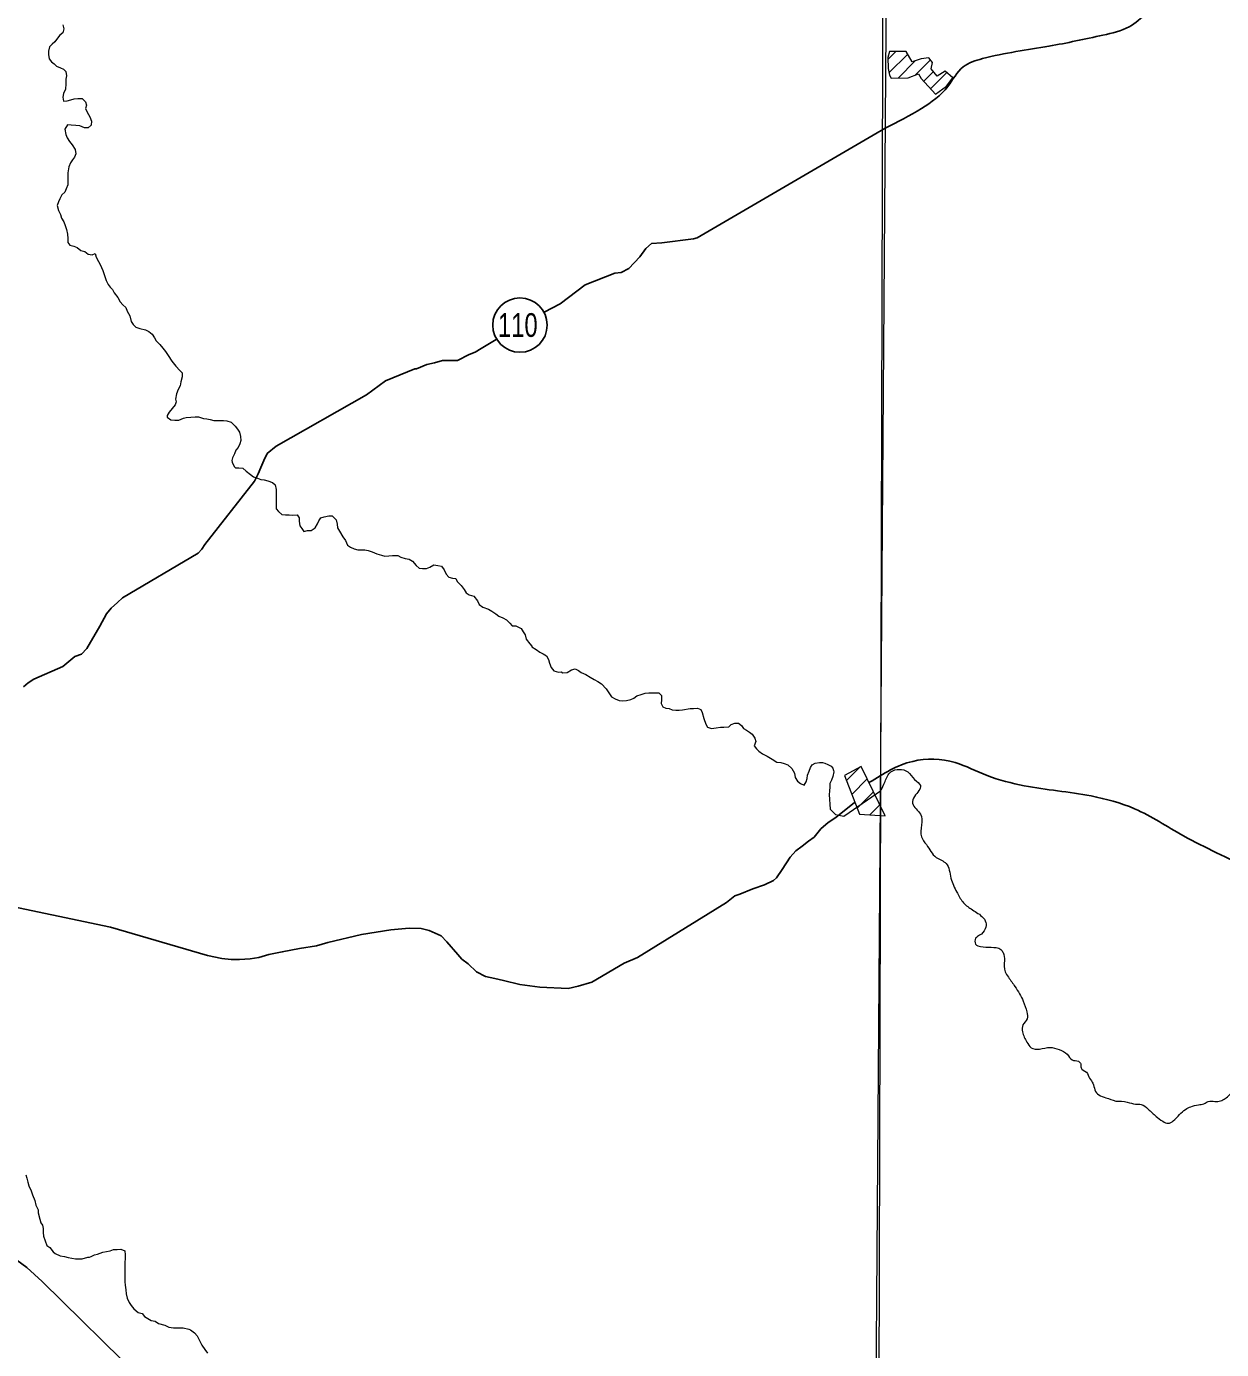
# Model space of a CAD drawing. Extents: x -1643653 to 4543381, y 1624270 to 13878484.
# Drawn here: x 615998 to 619526, y 8902830 to 8906736 of the extents above; entities that cross this region are included whole.
import ezdxf
from ezdxf.enums import TextEntityAlignment as Align

# ---------------------------------------------------------------- set-up
doc = ezdxf.new("R2010")
doc.units = 0
doc.header["$LTSCALE"] = 200
doc.layers.add('6', color=7, linetype='Continuous', lineweight=13)
doc.layers.add('60', color=7, linetype='Continuous', lineweight=13)

msp = doc.modelspace()

# ---------------------------------------------------------------- linework, layer by layer
at = {"layer": '6'}
for p, q in [((618541.3, 8906638.8), (618565.2, 8906662.7)), ((618544.4, 8906599.4), (618599.8, 8906654.9)), ((618571.2, 8906583.9), (618623, 8906635.6)), ((618623.2, 8906593.4), (618667.4, 8906637.6)), ((618647.2, 8906575), (618675.6, 8906603.4)), ((618667.4, 8906552.7), (618715.2, 8906600.5)), ((618419.3, 8904510), (618459.5, 8904550.2)), ((618435.1, 8904469.2), (618480.5, 8904514.6)), ((618451, 8904428.5), (618499.1, 8904476.6)), ((618488.1, 8904409.1), (618517.7, 8904438.6))]:
    msp.add_line(p, q, dxfattribs=at)
for points in [[(618663, 8924716.1), (618558.3, 8909803.7), (618456.5, 8896026.7)], [(616107.9, 8906729.7), (616104.8, 8906717.5), (616096.6, 8906710.4), (616089.4, 8906702.3), (616081.2, 8906691.2), (616074, 8906684.1), (616065.8, 8906676), (616062.7, 8906663.8), (616062.6, 8906653.6), (616064.6, 8906641.3), (616071.6, 8906632.1), (616079.7, 8906626), (616086.8, 8906618.8), (616097.9, 8906614.6), (616107.1, 8906610.5), (616114.1, 8906603.3), (616116.1, 8906591.1), (616114, 8906580.9), (616113.9, 8906566.7), (616112.8, 8906551.4), (616107.6, 8906538.2), (616105.5, 8906528), (616107.4, 8906515.8), (616117.6, 8906516.7), (616128.8, 8906519.7), (616139, 8906522.7), (616149.2, 8906523.6), (616162.4, 8906523.6), (616172.5, 8906514.3), (616175.5, 8906504.1), (616172.4, 8906493.9), (616177.4, 8906483.7), (616185.4, 8906469.4), (616189.4, 8906457.2), (616189.3, 8906444.9), (616180.1, 8906436.8), (616168.9, 8906436.9), (616155.8, 8906443.1), (616143.6, 8906444.2), (616130.3, 8906445.3), (616119.2, 8906446.4), (616110.9, 8906433.2), (616113.9, 8906417.9), (616117.9, 8906407.7), (616124.9, 8906396.4), (616133, 8906387.2), (616142.1, 8906372.9), (616144, 8906360.7), (616139.9, 8906350.5), (616133.7, 8906342.4), (616127.6, 8906334.3), (616123.4, 8906322.1), (616120.2, 8906304.8), (616120.1, 8906290.5), (616120.1, 8906279.3), (616120, 8906269.1), (616114.8, 8906256.9), (616110.7, 8906246.8), (616102.5, 8906239.7), (616096.3, 8906227.5), (616092.2, 8906218.4), (616088, 8906208.2), (616092, 8906192.9), (616098, 8906181.7), (616101, 8906170.4)], [(616104.9, 8906740.9), (616107.9, 8906729.7)], [(616101, 8906170.4), (616108, 8906159.2), (616112, 8906149), (616116, 8906136.7), (616119, 8906123.4), (616119.9, 8906110.2), (616119.8, 8906099), (616125.9, 8906090.8), (616138.1, 8906087.7), (616147.2, 8906083.5), (616158.3, 8906075.3), (616170.5, 8906072.2), (616179.6, 8906064), (616191.8, 8906061.9), (616201, 8906065.9), (616204, 8906055.7), (616211, 8906042.4), (616215, 8906033.2), (616223, 8906015.8), (616229, 8905998.5), (616233, 8905986.2), (616239, 8905975), (616245.1, 8905966.8), (616252.1, 8905959.6), (616257.2, 8905950.4), (616267.2, 8905936.1), (616274.3, 8905923.8), (616282.3, 8905914.6), (616291.4, 8905906.4), (616295.4, 8905896.2), (616303.5, 8905881.8), (616307.4, 8905865.5), (616312.5, 8905856.3), (616320.5, 8905849.1), (616332.7, 8905845), (616349, 8905840.8), (616359.1, 8905835.6)], [(616359.1, 8905835.6), (616369.2, 8905828.4), (616376.3, 8905817.2), (616380.3, 8905808), (616391.4, 8905797.7), (616400.5, 8905786.5), (616408.5, 8905777.2), (616416.6, 8905765), (616426.7, 8905748.6), (616438.8, 8905733.2), (616450.9, 8905720.9), (616458, 8905713.8), (616457.9, 8905701.6), (616453.7, 8905687.3), (616451.6, 8905675.1), (616445.4, 8905664.9), (616441.2, 8905651.7), (616438.2, 8905636.4), (616439.5, 8905627.9), (616437, 8905619.4), (616419.4, 8905598.1), (616413.4, 8905587.8), (616413.3, 8905582.6), (616424.5, 8905575.4), (616435.6, 8905574.3), (616447.8, 8905574.3), (616461.1, 8905580.3), (616469.2, 8905581.7), (616483.5, 8905583.2), (616495.7, 8905584.1), (616505.6, 8905583.6), (616520.7, 8905578.7), (616530.4, 8905578.1), (616540.1, 8905575.7), (616551, 8905573.2), (616566.8, 8905573.2), (616579.5, 8905573.2), (616589.8, 8905572), (616602.6, 8905568.4), (616607.5, 8905563.1), (616614.5, 8905555.9), (616620.6, 8905547.7), (616626.6, 8905538.5), (616629.6, 8905526.2), (616630.5, 8905514), (616627.4, 8905503.8), (616623.2, 8905493.7), (616616.5, 8905485.2), (616611.7, 8905474.3), (616606.2, 8905463.3), (616604.4, 8905455.4), (616605, 8905450), (616611.1, 8905437.2), (616614.7, 8905433.6), (616624.9, 8905433.6), (616637.1, 8905432.5), (616646.2, 8905423.2), (616659.3, 8905414), (616668.4, 8905406.8), (616679.6, 8905402.6), (616689.8, 8905398.5), (616699.9, 8905397.4), (616710.1, 8905395.3), (616724.3, 8905390.1), (616732.4, 8905382.9)], [(616732.4, 8905382.9), (616735.3, 8905369.7), (616735.3, 8905359.5), (616735.2, 8905344.2), (616735, 8905325.9), (616734.9, 8905312.6), (616742, 8905304.4), (616752.1, 8905295.2), (616762.3, 8905294.1), (616773.5, 8905294.1), (616784.7, 8905294), (616796.9, 8905294.9), (616802.9, 8905285.7), (616802.8, 8905275.5), (616804.8, 8905262.3), (616810.8, 8905254.1), (616816.9, 8905244.9), (616828.1, 8905247.9), (616838.2, 8905247.8), (616850.5, 8905255.9), (616856.7, 8905268.1), (616860.8, 8905277.2), (616867, 8905285.3), (616877.2, 8905288.3), (616890.4, 8905291.3), (616900.6, 8905291.2), (616912.7, 8905279.9), (616915.7, 8905266.7), (616916.6, 8905256.5), (616921.7, 8905246.2), (616931.7, 8905229.9), (616939.8, 8905218.6), (616945.8, 8905205.3), (616954.9, 8905199.2), (616965, 8905194), (616976.2, 8905190.9), (616986.4, 8905190.8)], [(616986.4, 8905190.8), (616996.5, 8905190.7), (617006.7, 8905189.7), (617018.9, 8905185.5), (617032.1, 8905179.3), (617046.3, 8905175.1), (617056.4, 8905172), (617067.6, 8905173), (617078.8, 8905174.9), (617094.1, 8905174.8), (617103.2, 8905169.7), (617116.4, 8905165.5), (617127.6, 8905163.4), (617137.7, 8905158.2), (617148.8, 8905144.9), (617156.9, 8905136.7), (617167.1, 8905135.7), (617179.3, 8905135.6), (617188.5, 8905139.6), (617200.7, 8905146.6), (617212.9, 8905144.5), (617223.1, 8905143.4), (617231.1, 8905132.2), (617237.1, 8905118.9), (617245.2, 8905110.7), (617255.4, 8905107.6), (617265.5, 8905106.5), (617269.5, 8905097.3), (617281.7, 8905086), (617289.7, 8905073.7), (617295.8, 8905064.5), (617304.9, 8905058.4), (617319.1, 8905054.2), (617329.2, 8905040.9), (617334.2, 8905029.7), (617345.3, 8905022.4), (617361.6, 8905016.2), (617371.7, 8905010.1), (617383.8, 8905001.8), (617392.9, 8904995.7), (617404.1, 8904990.5), (617415.2, 8904984.3), (617425.3, 8904975.1), (617432.4, 8904966.9), (617442.6, 8904966.8), (617458.8, 8904958.6), (617464.8, 8904949.3), (617469.9, 8904940.1), (617472.8, 8904927.9), (617483.6, 8904913.2), (617490, 8904906.8), (617490, 8904904.7), (617503.1, 8904897.1), (617513.3, 8904888.9), (617523.5, 8904884.2), (617532.9, 8904877.9), (617539.1, 8904867), (617542.2, 8904856.1), (617546.9, 8904843.6), (617554.7, 8904834.2), (617568.8, 8904829.5), (617576.6, 8904831.1), (617581.2, 8904827.9), (617594.2, 8904829.3), (617607.5, 8904836.4)], [(617607.5, 8904836.4), (617617.7, 8904839.4), (617627.8, 8904835.2), (617635.9, 8904829.1), (617649.1, 8904822.9), (617662.3, 8904815.6), (617674.4, 8904808.4), (617684.6, 8904802.2), (617695.7, 8904795.1), (617709.9, 8904780.7), (617716.9, 8904769.4), (617725, 8904757.2), (617736.1, 8904751), (617748.3, 8904746.8), (617758.4, 8904745.8), (617769.6, 8904746.7), (617781.9, 8904749.7), (617791.1, 8904753.7), (617800.2, 8904759.7), (617812.5, 8904763.7), (617824.7, 8904767.7), (617835.9, 8904768.7), (617855.2, 8904768.6), (617865.4, 8904768.5), (617872.5, 8904761.3), (617872.4, 8904748.1), (617872.3, 8904737.9), (617876.3, 8904727.7), (617885.5, 8904723.5), (617895.6, 8904722.4), (617904.7, 8904718.3), (617914.9, 8904718.2), (617925.1, 8904718.2), (617935.3, 8904719.1), (617957.7, 8904723.1), (617967.8, 8904723), (617979, 8904724)], [(617979, 8904724), (617989.2, 8904719.8), (617993.2, 8904710.6), (617998.2, 8904693.3), (618004.1, 8904676.9), (618008.2, 8904667.7), (618020.3, 8904663.6), (618034.6, 8904665.5), (618046.8, 8904667.5), (618057, 8904667.4), (618071.2, 8904668.3), (618078.4, 8904675.4), (618089.6, 8904679.4), (618099.8, 8904679.4), (618108.9, 8904672.2), (618114.9, 8904664), (618124.1, 8904658.8), (618132.2, 8904652.7), (618140.2, 8904646.5), (618148.3, 8904635.3), (618151.3, 8904625.1), (618146.1, 8904612.9), (618153.2, 8904603.6), (618160.2, 8904596.5), (618171.4, 8904589.3), (618184.6, 8904582.1), (618199.8, 8904572.8), (618212.9, 8904564.6), (618225.1, 8904563.4), (618235.3, 8904560.3), (618245.4, 8904556.2), (618257.6, 8904545.9), (618265.6, 8904531.6), (618267.5, 8904519.4), (618274.6, 8904508.1), (618283.7, 8904500.9), (618293.8, 8904496.8), (618300, 8904505.9), (618303.1, 8904516.1), (618304.2, 8904526.3), (618309, 8904537.8), (618312.5, 8904548.5), (618317.6, 8904556.7), (618326.8, 8904561.1), (618339.4, 8904562.8), (618348.3, 8904562.8), (618355.5, 8904561.1), (618364.4, 8904557.5), (618373.3, 8904552.1), (618378.7, 8904546.7), (618380.5, 8904539.6), (618381.6, 8904536), (618378.4, 8904521.7), (618374.3, 8904511.6), (618370.2, 8904501.4), (618370.1, 8904491.2), (618369, 8904479), (618367.9, 8904468.8), (618370.7, 8904425), (618386.8, 8904409.6), (618410.9, 8904405.3), (618427, 8904416), (618519.7, 8904479.2)], [(615995.5, 8903346), (615998.5, 8903335.8), (616001.4, 8903324.6), (616004.4, 8903313.3), (616011.4, 8903299), (616015.4, 8903286.8), (616022.4, 8903270.4), (616025.4, 8903256.1), (616032.4, 8903242.8), (616031.9, 8903233.8), (616036.9, 8903215.3), (616040.3, 8903203.6), (616045.3, 8903196.9), (616047.3, 8903187.7), (616047.2, 8903175.5), (616048.1, 8903164.3), (616053.1, 8903151), (616058.1, 8903136.7), (616067.2, 8903131.6), (616077.1, 8903118.2), (616082.1, 8903113.2), (616097.1, 8903106.5)], [(616097.1, 8903106.5), (616110.5, 8903104.8), (616120.6, 8903101.5), (616142.3, 8903098.2), (616162.4, 8903098.2), (616179.1, 8903103.2), (616184.1, 8903103.2), (616189.1, 8903104.8), (616199.2, 8903109.9), (616207.5, 8903111.5), (616223.8, 8903117.3), (616234, 8903119.3), (616245.2, 8903121.3), (616254.4, 8903125.3), (616265.6, 8903125.2), (616276.8, 8903126.2), (616287.9, 8903121), (616288.8, 8903109.8), (616288.8, 8903098.6), (616288.7, 8903087.4), (616288.6, 8903076.2), (616288.5, 8903059.9), (616288.4, 8903040.5), (616288.3, 8903030.3), (616289.3, 8903020.1), (616291.2, 8903005.8), (616292.1, 8902994.6), (616295.1, 8902981.4), (616301.1, 8902969.1), (616307.2, 8902959.9), (616315.2, 8902949.7), (616327.9, 8902939.1), (616339.5, 8902936.3), (616346.3, 8902927.4), (616366.4, 8902915.6), (616378.1, 8902914), (616388.1, 8902907.3)], [(616388.1, 8902907.3), (616406.5, 8902902.2), (616418.2, 8902895.6), (616431.6, 8902893.9), (616441.7, 8902893.9), (616460.1, 8902893.9), (616476.8, 8902890.5), (616482.6, 8902888.5), (616493.8, 8902879.2), (616501.8, 8902870), (616510.9, 8902852.7), (616515.9, 8902842.4), (616524, 8902830.2), (616532, 8902818.9)]]:
    msp.add_lwpolyline(points, dxfattribs=at)
for points in [[(618535.2, 8909853.3), (607574.3, 8909890.7), (607543.3, 8898835.3), (618504.2, 8898795.8)], [(618595.3, 8906663), (618545.6, 8906662.6), (618541.1, 8906644.9), (618542, 8906612), (618545.6, 8906593), (618551, 8906583.5), (618601.6, 8906584.4), (618631.9, 8906597.1), (618640, 8906583.1), (618681.6, 8906537), (618714.5, 8906560), (618732.6, 8906584.9), (618710.5, 8906604.7), (618686.5, 8906589.8), (618669.4, 8906611.1), (618673, 8906630.5), (618662.6, 8906643.6), (618639.6, 8906640.9), (618612.5, 8906632.3)], [(618462.3, 8904551.7), (618413.4, 8904525.1), (618457.8, 8904411), (618533.6, 8904406.1)]]:
    msp.add_lwpolyline(points, close=True, dxfattribs=at)
at = {"layer": '6', "lineweight": 25}
for points in [[(618533.2, 8906436.6), (617978.2, 8906112.6), (617967, 8906109.6), (617874.3, 8906097.6), (617843.7, 8906095.6), (617826.3, 8906081.3), (617808.9, 8906055.9), (617776.2, 8906022.3), (617753.7, 8906010.2), (617735.4, 8906008.2), (617647.6, 8905973.7), (617574.1, 8905917.8), (617526.6, 8905893.4)], [(617384.3, 8905811.9), (617340.2, 8905785.8), (617322.9, 8905774.6), (617304.5, 8905767.5), (617270.8, 8905750.2), (617226, 8905750.3), (617202.5, 8905743.2), (617180.1, 8905738.2), (617149.5, 8905726), (617144.4, 8905726), (617057.7, 8905690.5), (617001.5, 8905648.8), (616735, 8905497.5), (616708.4, 8905475.2), (616698.2, 8905454.8), (616689.9, 8905434.4), (616681.7, 8905415.1), (616671.4, 8905393.7), (616524, 8905206.5), (616515.8, 8905193.3), (616504.6, 8905181.1), (616281, 8905049.1), (616266.7, 8905035.8), (616248.2, 8905018.6), (616233.9, 8905002.3), (616214.4, 8904965.6), (616176.5, 8904899.5), (616160.1, 8904883.2), (616140.7, 8904876.1), (616105, 8904846.6), (616019.2, 8904809.1), (616002.9, 8904798.9), (615988.6, 8904786.7)], [(618442.8, 8904444.9), (618387.6, 8904401.3), (618365.2, 8904386.1), (618343.7, 8904367.8), (618323.2, 8904343.3), (618306.9, 8904331.1), (618288.5, 8904315.9), (618269.1, 8904302.7), (618252.7, 8904283.3), (618229.2, 8904247.7), (618212.8, 8904222.3), (618203.6, 8904215.2), (618177, 8904202), (618142.3, 8904189.8), (618104.6, 8904174.6), (618089.3, 8904169.5), (618064.8, 8904150.2), (617802.3, 8903987.7), (617762.5, 8903970.5), (617667.6, 8903914.6), (617626.8, 8903902.4), (617597.2, 8903896.4), (617513.6, 8903899.6), (617454.6, 8903907.9), (617406.7, 8903919.2), (617380.3, 8903925.3), (617352.8, 8903931.5), (617326.3, 8903944.8), (617302, 8903969.3), (617283.7, 8903982.5), (617271.5, 8903996.8), (617239, 8904033.6), (617221.8, 8904051.9), (617187.2, 8904067.3), (617162.8, 8904073.4), (617128.1, 8904074.5), (617074.1, 8904069.5), (616987.5, 8904055.4), (616887.5, 8904032.2), (616853.9, 8904022.1), (616803.9, 8904014), (616752.9, 8904003.9), (616713.2, 8903996.8), (616683.6, 8903987.7), (616658.1, 8903983.7), (616626.5, 8903981.7), (616602.1, 8903981.8), (616574.6, 8903984.9), (616532.8, 8903993.1), (616245.8, 8904077.2), (615725.6, 8904186.1)], [(615969.1, 8903093.5), (615998.6, 8903072.1), (616044.3, 8903031.2), (616338.7, 8902741.3)]]:
    msp.add_lwpolyline(points, dxfattribs=at)
msp.add_circle((617454.9, 8905854.7), 80.3, dxfattribs=at)
for points in [[(618533.2, 8906436.6), (618640.7, 8906494.3), (618718.4, 8906559.7), (618763.3, 8906617), (618820.6, 8906641.5), (619016.9, 8906678.3), (619176.3, 8906711), (619254, 8906735.6), (619352.2, 8906825.5), (619442.1, 8906899.1), (619532.1, 8907042.2), (619630.2, 8907238.5), (619687.5, 8907398), (619720.2, 8907528.8), (619740.6, 8907635.2), (619765.2, 8907684.2), (619806, 8907741.5), (619834.7, 8907831.4), (619871.5, 8907884.6), (619957.3, 8907905), (620026.8, 8907892.8), (620094.6, 8907904)], [(618487.4, 8904504.8), (618614.5, 8904566.7), (618739.5, 8904562.9), (618834.2, 8904525), (618944, 8904494.7), (619141, 8904464.4), (619269.8, 8904426.5), (619413.7, 8904347), (619610.7, 8904248.5), (619898.6, 8904070.5), (620175.1, 8903918.9), (620288.7, 8903884.9), (620489.5, 8903873.5), (620815.2, 8903858.3), (621019.8, 8903831.8), (621319, 8903718.2), (621610.7, 8903631.1), (621785, 8903608.3), (621841.8, 8903604.6), (621917.5, 8903551.5), (622012.2, 8903479.6), (622084.2, 8903426.5), (622194.1, 8903396.2), (622315.3, 8903388.6)]]:
    msp.add_spline(points, degree=3, dxfattribs=at)
at = {"layer": '6'}
for points in [[(618519.7, 8904479.2), (618532.8, 8904506.8), (618550.3, 8904535.8), (618599.7, 8904535.8), (618620.1, 8904512.6), (618637.5, 8904495.1), (618620.1, 8904463.1), (618614.2, 8904442.8), (618637.5, 8904410.8), (618640.4, 8904378.8), (618640.4, 8904343.9), (618655, 8904320.7), (618684, 8904282.9), (618713.1, 8904265.4), (618727.6, 8904221.8), (618744.8, 8904180.8), (618762.3, 8904151.5), (618786.7, 8904131), (618818.9, 8904108.6), (618830.6, 8904091), (618828.7, 8904072.5), (618812.1, 8904053), (618800.4, 8904044.2), (618800.4, 8904026.6), (618815, 8904019.8), (618846.2, 8904017.8), (618874.5, 8904011), (618881.3, 8904002.2), (618885.2, 8903978.8), (618887.2, 8903945.6), (618897, 8903929), (618916.5, 8903901.7), (618940.9, 8903858.8), (618951.6, 8903826.6), (618952.6, 8903806.1), (618939.9, 8903788.6), (618938.9, 8903768.1), (618943.8, 8903752.4), (618951.6, 8903737.8), (618964.3, 8903721.2), (618988.7, 8903717.3), (619019.9, 8903722.2), (619047.2, 8903715.4), (619070.6, 8903701.7), (619085.3, 8903685.1), (619103.8, 8903681.2), (619110.6, 8903673.4), (619111.6, 8903661.7), (619127.2, 8903649.3), (619137, 8903630.8), (619146.7, 8903616.1), (619152.6, 8903596.6), (619164.3, 8903581.9), (619184.8, 8903573.2), (619214.1, 8903563.4)], [(619214.1, 8903563.4), (619248.2, 8903560.5), (619272.6, 8903554.6), (619289.2, 8903553.6), (619309.7, 8903540), (619333.1, 8903518.5), (619352.6, 8903503.8), (619369.2, 8903498), (619383.8, 8903504.8), (619402.4, 8903524.3), (619419.9, 8903539), (619435.5, 8903546.8), (619458, 8903552.7), (619474.6, 8903555.6), (619487.2, 8903562.4), (619506.8, 8903562.4), (619523.3, 8903564.4), (619537, 8903571.2), (619549.7, 8903581.9), (619561.4, 8903593.7), (619579, 8903591.7), (619602.4, 8903587.8), (619613.1, 8903587.8), (619630.7, 8903597.6), (619638.5, 8903604.4), (619648.2, 8903604.4), (619655.1, 8903595.6), (619667.8, 8903581.9), (619683.8, 8903571.2), (619694.6, 8903557.5), (619699.5, 8903545.8), (619709.2, 8903539), (619720, 8903533.1), (619740.4, 8903528.2), (619752.2, 8903520.4), (619759, 8903504.8), (619761.9, 8903487.2), (619771.7, 8903470.7), (619786.2, 8903450.4), (619800.9, 8903433.1), (619809.2, 8903423.3), (619815.2, 8903415), (619814.8, 8903409.7), (619805.4, 8903393.9), (619797.1, 8903375.4), (619797.9, 8903364.1), (619804.7, 8903355.4), (619816.7, 8903342.2), (619828.8, 8903330.9), (619839, 8903321.1), (619849.5, 8903308.7), (619861.2, 8903293.6), (619870.6, 8903279.3), (619878.6, 8903264.2), (619888, 8903248)]]:
    msp.add_spline(points, degree=3, dxfattribs=at)
at = {"layer": '60', "lineweight": 25}
msp.add_spline([(814781, 9009175.5), (814787.2, 9009173.4), (814796.9, 9009173.4), (814799.4, 9009172.4), (814805.1, 9009174.5), (814805.6, 9009176.5), (814811.7, 9009179.5), (814811.7, 9009179.5), (814801.5, 9009181), (814790.7, 9009181.5), (814784.1, 9009183.1), (814777.4, 9009185.1), (814778.4, 9009175.5)], degree=3, dxfattribs=at)

# ---------------------------------------------------------------- texts
at = {"layer": '6', "width": 0.75}
msp.add_text('110', height=70, dxfattribs=at).set_placement((617448.6, 8905820), align=Align.CENTER)

doc.saveas('drawing.dxf')
